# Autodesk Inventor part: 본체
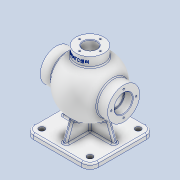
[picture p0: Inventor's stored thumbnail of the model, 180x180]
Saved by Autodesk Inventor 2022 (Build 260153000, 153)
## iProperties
Created: 2024-04
Part Number: 본체
Material: 알루미늄 6061
Document SubType Name: Modeling
Designer: Admin
Density: 2.7 g/cm^3
Appearance: 알루미늄 - 평지
Mass: 1526.72 g
Surface Area: 1173.82 cm^2
Volume: 565.453 cm^3
Author: Admin
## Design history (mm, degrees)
sketch "스케치1"
  geometry: L1 (-141.455, 0)-(183.523, 0); L2 (-65, 0)-(-65, 31); L3 (-65, 31)-(-44.215, 31); L4 (65, 0)-(65, 31); L5 (65, 31)-(44.215, 31); L6 (0, -10.8)-(0, 64.8) reference; A1 r 54 centre (0, 0) between (54, 0) and (-54, 0); 1 further point
  constraints: 10 end point, 5 point on line, 4 point on circle, 2 perpendicular, 2 vertical, 1 centre point, 1 coincident, 1 horizontal, 1 other
  dimensions: "d0" = 108 diameter of A1; "d1" = 62 diameter of L3 L1; "d2" = 62 diameter of L5 L1; "d3" = 130 distance between parallel lines of L4 L2
revolve "회전1" sketch "스케치1" stored, may be unused: angle "d4" = 90 deg
node "작업 평면1"
sketch "스케치2"
  geometry: L1 (62.5, 62.5)-(-62.5, 62.5); L2 (-62.5, 62.5)-(-62.5, -62.5); L3 (-62.5, -62.5)-(62.5, -62.5); L4 (62.5, -62.5)-(62.5, 62.5); L5 (62.5, 62.5)-(-62.5, -62.5); L6 (-62.5, 62.5)-(62.5, -62.5); 1 further point
  constraints: 12 end point, 2 midpoint, 2 parallel, 1 horizontal, 1 perpendicular
  dimensions: "d6" = 125 distance of L3.end L2.end; "d7" = 125 distance of L2.end L1.end
extrude "돌출1" join sketch "스케치2" distance "d8" = 10; taper "d9" = 0 deg
sketch "스케치3"
  geometry: L1 (-75, 62.5)-(-75, -62.5) reference; L2 (-75, -50.5)-(-25.518, -32.49); L3 (-25.518, -32.49)-(-25.518, 32.49); L4 (-25.518, 32.49)-(-75, 50.5); L5 (-85, -62.5)-(-75, -62.5) reference; L6 (-85, 62.5)-(-75, 62.5) reference; 1 further point
  constraints: 6 end point, 2 point on line, 1 parallel
  dimensions: "d10" = 12 distance from line of L5 L2.start; "d11" = 12 distance from line of L6 L4.end; "d12" = 20 deg angle of L5 L2; "d13" = 20 deg angle of L6 L4; "d14" = 49.48158 distance between parallel lines of L1 L3
extrude "돌출2" join sketch "스케치3" stored distance "d15" = 8; taper "d16" = 0 deg
sketch "스케치4"
  geometry: L1 (62.5, -75)-(-62.5, -75) reference; L2 (-50.5, -75)-(-32.494, -25.53); L3 (-32.494, -25.53)-(32.494, -25.53); L4 (32.494, -25.53)-(50.5, -75); L5 (-62.5, -85)-(-62.5, -75) reference; L6 (62.5, -85)-(62.5, -75) reference; 1 further point
  constraints: 6 end point, 2 point on line, 1 parallel
  dimensions: "d17" = 12 distance from line of L5 L2.start; "d18" = 12 distance from line of L6 L4.end; "d19" = 20 deg angle of L5 L2; "d20" = 20 deg angle of L6 L4; "d21" = 49.46992 distance between parallel lines of L1 L3
extrude "돌출3" join sketch "스케치4" stored distance "d22" = 8; taper "d23" = 0 deg
sketch "스케치5"
  geometry: L1 (-104.576, 0)-(135.869, 0); L2 (-65, -31)-(-65, 31) reference; L3 (-65, 0)-(-49, 0); L4 (-49, 0)-(-49, 17.5); L5 (-49, 17.5)-(-65, 17.5); L6 (-65, 17.5)-(-65, 0); L7 (-49, 0)-(-41.364, 0); L8 (-41.364, 0)-(-41.364, 15); L9 (-41.364, 15)-(-49, 15); L10 (-49, 15)-(-49, 0); L11 (65, -31)-(65, 31) reference; L12 (65, 0)-(49, 0); L13 (49, 0)-(49, 17.5); L14 (49, 17.5)-(65, 17.5); L15 (65, 17.5)-(65, 0); L16 (49, 0)-(41.364, 0); L17 (41.364, 0)-(41.364, 15); L18 (41.364, 15)-(49, 15); L19 (49, 15)-(49, 0); A1 r 44 centre (0, 0) between (41.364, 15) and (-41.364, 15); 7 further points
  constraints: 34 end point, 8 parallel, 5 horizontal, 4 perpendicular, 2 midpoint, 2 point on circle, 1 centre point, 1 coincident, 1 point on line
  dimensions: "d24" = 88 diameter of A1; "d25" = 35 diameter of L5 L1; "d26" = 30 diameter of L9 L1; "d27" = 35 diameter of L14 L1; "d28" = 30 diameter of L18 L1; "d29" = 16 distance between parallel lines of L2 L10; "d30" = 16 distance between parallel lines of L15 L19
revolve "회전2" sketch "스케치5" stored, may be unused: angle "d31" = 90 deg
sketch "스케치6"
  geometry: L1 (0, -112.8)-(0, 81.8) reference; 2 further points
  constraints: 1 point on line
  dimensions: "d32" = 24 distance of point (0, 0) point (0, 24)
hole "구멍1" sketch "스케치6" at (0, 24) diameter "d33" = 3.242; stored, may be unused: countersink angle "d37" = 90 deg, drill point angle "d39" = 118 deg; dims "d34" = 12, "d35" = 4, "d36" = 2, "d38" = 15
sketch "스케치7"
  geometry: L1 (0, -112.8)-(0, 81.8) reference; 2 further points
  constraints: 1 point on line
  dimensions: "d43" = 24 distance of point (0, 0) point (0, 24)
hole "구멍2" sketch "스케치7" at (0, 24) diameter "d44" = 3.242; stored, may be unused: countersink angle "d48" = 90 deg, drill point angle "d50" = 118 deg; dims "d45" = 12, "d46" = 4, "d47" = 2, "d49" = 15
node "작업 평면2"
sketch "스케치8"
  geometry: C1 r 27 at (0, 0); 1 further point
  constraints: 1 centre point, 1 coincident
  dimensions: "d55" = 54 diameter of C1
extrude "돌출4" join sketch "스케치8" stored distance "d56" = 8; taper "d57" = 0 deg
sketch "스케치9"
  geometry: C1 r 13 at (0, 0); 1 further point
  constraints: 1 centre point, 1 coincident
  dimensions: "d58" = 26 diameter of C1
extrude "돌출5" cut sketch "스케치9" stored distance "d59" = 10; taper "d60" = 0 deg
sketch "스케치10"
  geometry: L1 (0, 87.5)-(0, -87.5) reference; 2 further points
  constraints: 1 point on line
  dimensions: "d61" = 20 distance of point (0, 0) point (0, 20)
hole "구멍3" sketch "스케치10" at (0, 20) diameter "d62" = 3.242; stored, may be unused: countersink angle "d66" = 90 deg, drill point angle "d68" = 118 deg; dims "d63" = 9, "d64" = 4, "d65" = 2, "d67" = 11
fillet "모깎기1" dims "d72" = 16
sketch "스케치11"
  geometry: A1 r 16 centre (-46.5, 46.5) between (-46.5, 62.5) and (-62.5, 46.5) reference; A2 r 16 centre (46.5, 46.5) between (62.5, 46.5) and (46.5, 62.5) reference; A3 r 16 centre (46.5, -46.5) between (46.5, -62.5) and (62.5, -46.5) reference; A4 r 16 centre (-46.5, -46.5) between (-62.5, -46.5) and (-46.5, -62.5) reference; 5 further points
  constraints: 4 coincident
hole "구멍4" sketch "스케치11" at (-46.5, 46.5), (46.5, 46.5), (46.5, -46.5), (-46.5, -46.5) diameter "d73" = 11; stored, may be unused: countersink angle "d77" = 90 deg, drill point angle "d79" = 118 deg; dims "d74" = 9, "d75" = 4, "d76" = 2, "d78" = 11
node "작업 평면3"
sketch "스케치12"
  geometry: L1 (-27, 65)-(27, 65) reference; L2 (-27, 65)-(-27, 46.765) reference; 2 further points
  constraints: 1 other
  dimensions: "d81" = 9 distance from line of L1 point (0, 56); "d82" = 27 distance from line of L2 point (0, 56)
feature "엠보싱1" sketch "스케치12" dims "d83" = 0.5, "d84" = 0
fillet "모깎기2" dims "d85" = 0.6
fillet "모깎기3" dims "d86" = 3
fillet "모깎기4" dims "d87" = 3
fillet "모깎기5" dims "d88" = 3
chamfer "모따기1" distance "d89" = 1; stored, may be unused: second distance "d90" = 2, angle "d91" = 45 deg
node "솔리드1"
pattern_circular "원형 패턴1" dims angle "d41" = 360 deg
pattern_circular "원형 패턴2" dims angle "d52" = 360 deg
pattern_circular "원형 패턴3" dims angle "d70" = 360 deg
feature "A9D066F2-1C7D-4E18-AEED-F7BC21143FA4" dims "d73" = 11, "d74" = 9, "d75" = 4, "d76" = 2, "d77" = 90 deg, "d78" = 11, "d79" = 118 deg
other parameters: "d5" = -85, "d80" = 27
